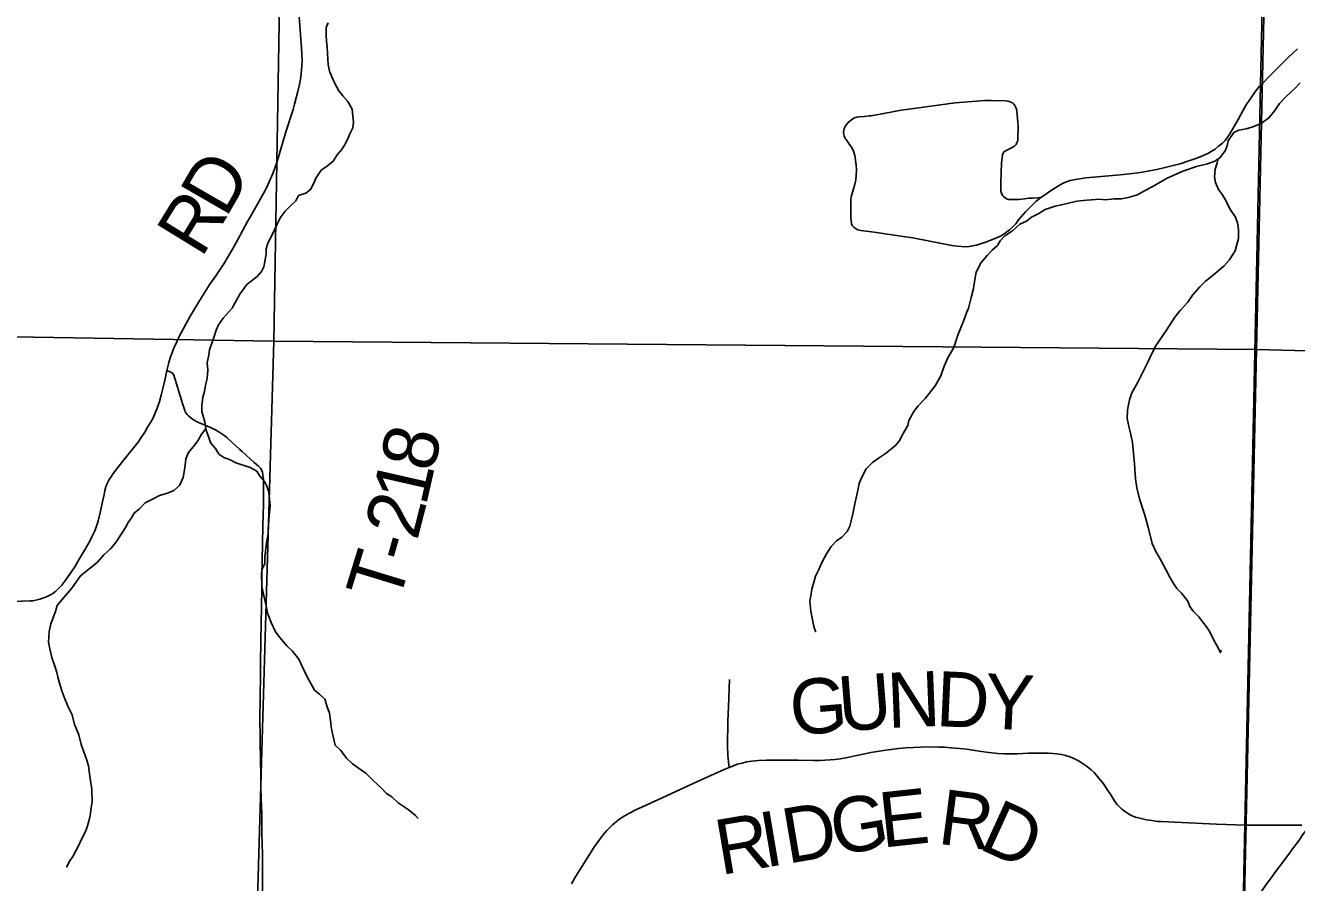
# Model space of a CAD drawing. Extents: x 0 to 34, y 0 to 22.
# Drawn here: x 5.283 to 6.594, y 15.364 to 16.248 of the extents above; entities that cross this region are included whole.
import ezdxf

# ---------------------------------------------------------------- set-up
doc = ezdxf.new("R2010")
doc.units = 0
for name, color, linetype in [('GM_X_Corporation', 7, 'Continuous'), ('GM_X_Interchange_Ramps', 7, 'Continuous'), ('GM_X_Interstate_Route', 7, 'Continuous'), ('GM_X_Major_Lake', 7, 'Continuous'), ('GM_X_Minor_Lake', 7, 'Continuous'), ('GM_X_Section', 7, 'Continuous'), ('GM_X_Township_Road_Text', 7, 'Continuous')]:
    doc.layers.add(name, color=color, linetype=linetype)

msp = doc.modelspace()

# ---------------------------------------------------------------- linework, layer by layer
at = {"layer": 'GM_X_Corporation'}
for points in [[(5.8464, 15.3632), (5.8509, 15.3708), (5.8574, 15.3813), (5.8649, 15.3933), (5.8702, 15.4016), (5.8766, 15.4105), (5.8803, 15.4152), (5.8828, 15.4182), (5.8859, 15.4213), (5.8888, 15.424), (5.8927, 15.4273), (5.8963, 15.43), (5.9006, 15.4327), (5.9055, 15.4356), (5.9129, 15.4394), (5.9198, 15.4426), (5.9317, 15.448), (5.9803, 15.4704), (6.0039, 15.4808), (6.0089, 15.483), (6.0136, 15.4849), (6.0174, 15.4863), (6.0224, 15.4876), (6.0269, 15.4887), (6.0324, 15.4894), (6.0392, 15.4902), (6.0476, 15.4906), (6.052, 15.4907), (6.0801, 15.4905), (6.0962, 15.4902), (6.1021, 15.4903), (6.1131, 15.4909), (6.1184, 15.4914), (6.1238, 15.4921), (6.1295, 15.4931), (6.1552, 15.4984), (6.1682, 15.5007), (6.1762, 15.5017), (6.1839, 15.5026), (6.1912, 15.5033), (6.1992, 15.5037), (6.2065, 15.504), (6.213, 15.5042), (6.2254, 15.504), (6.2313, 15.5039), (6.2381, 15.5034), (6.2509, 15.5022), (6.2563, 15.5015), (6.2671, 15.5), (6.2771, 15.4986), (6.2862, 15.4976), (6.2931, 15.4972), (6.2983, 15.4971), (6.3063, 15.4972), (6.3178, 15.4977), (6.3256, 15.4979), (6.3386, 15.4978), (6.3431, 15.4976), (6.3472, 15.497), (6.3519, 15.4963), (6.3559, 15.4954), (6.3595, 15.4942), (6.3631, 15.4929), (6.3661, 15.4916), (6.3695, 15.4898), (6.3733, 15.4875), (6.3774, 15.4847), (6.3825, 15.4806), (6.3857, 15.4777), (6.3871, 15.4763), (6.3926, 15.4697), (6.3951, 15.4663), (6.3989, 15.4605), (6.4035, 15.4537), (6.4071, 15.448), (6.4094, 15.445), (6.4118, 15.4424), (6.4141, 15.44), (6.4168, 15.4379), (6.4199, 15.4358), (6.4228, 15.4341), (6.4255, 15.4327), (6.4284, 15.4318), (6.434, 15.4303), (6.4396, 15.4291), (6.4452, 15.4282), (6.4511, 15.4275), (6.4548, 15.4272), (6.4761, 15.4262), (6.5117, 15.4247), (6.5414, 15.4237), (6.5471, 15.4235)], [(6.5452, 15.3343), (6.5495, 15.3413), (6.5548, 15.3499), (6.5578, 15.3549), (6.563, 15.3623), (6.5675, 15.3683), (6.5735, 15.3765), (6.5781, 15.3825), (6.583, 15.3891), (6.5864, 15.3936), (6.5904, 15.3992), (6.594, 15.404), (6.5973, 15.4086), (6.6007, 15.4135), (6.6049, 15.4191), (6.6077, 15.4229)], [(6.5471, 15.4235), (6.5841, 15.4236), (6.5999, 15.4237)]]:
    msp.add_lwpolyline(points, dxfattribs=at)
at = {"layer": 'GM_X_Interchange_Ramps'}
msp.add_lwpolyline([(2.1, 17.9098), (2.1, 14.1), (6.5113, 14.1), (6.5389, 15.3228), (6.5411, 15.4243), (6.5572, 16.1864), (6.5647, 16.5359), (6.5883, 17.471), (6.5943, 17.9356)], dxfattribs=at)
msp.add_lwpolyline([(6.5113, 14.1), (8.9, 14.1), (8.9, 17.8921), (8.5492, 17.9006), (8.3297, 17.9059), (7.6027, 17.9156), (6.5943, 17.9356), (6.5883, 17.471), (6.5647, 16.5359), (6.5572, 16.1864), (6.5411, 15.4243), (6.5389, 15.3228)], close=True, dxfattribs=at)
at = {"layer": 'GM_X_Interstate_Route'}
for points in [[(5.2695, 15.6542), (5.2879, 15.6547), (5.2906, 15.655), (5.2938, 15.6556), (5.2979, 15.6566), (5.3022, 15.658), (5.3056, 15.6592), (5.3089, 15.661), (5.3113, 15.6625), (5.3143, 15.6649), (5.3171, 15.6675), (5.3205, 15.6711), (5.3226, 15.6737), (5.3303, 15.6844), (5.334, 15.6899), (5.3396, 15.6994), (5.3448, 15.7081), (5.3495, 15.7165), (5.3517, 15.7209), (5.3545, 15.727), (5.3564, 15.7319), (5.3581, 15.737), (5.3592, 15.7414), (5.3602, 15.7458), (5.3618, 15.7537), (5.3642, 15.7646), (5.365, 15.7686), (5.3661, 15.7725), (5.3674, 15.7758), (5.3693, 15.7798), (5.3718, 15.7835), (5.3736, 15.786), (5.3831, 15.7986), (5.3992, 15.8186), (5.4026, 15.8234), (5.4062, 15.8288), (5.4091, 15.8338), (5.4121, 15.8387), (5.4144, 15.843), (5.4166, 15.8476), (5.4189, 15.8535), (5.4212, 15.8603), (5.4231, 15.8668), (5.4249, 15.8738), (5.4271, 15.8839), (5.4289, 15.8922), (5.4293, 15.8936), (5.4311, 15.9006), (5.4328, 15.9064), (5.4343, 15.9107), (5.4358, 15.9146), (5.4395, 15.9227), (5.4418, 15.9273), (5.4531, 15.9484), (5.4556, 15.9528), (5.4618, 15.9631), (5.4646, 15.9676), (5.4733, 15.9813), (5.4796, 15.9901), (5.4876, 16.0024), (5.4922, 16.0098), (5.4966, 16.0173), (5.5017, 16.0267), (5.5123, 16.0459), (5.5153, 16.0512), (5.529, 16.0754), (5.5319, 16.0808), (5.536, 16.0898), (5.5383, 16.0956), (5.5404, 16.1009), (5.5427, 16.1078), (5.551, 16.1359), (5.5521, 16.1396), (5.5591, 16.1613), (5.5607, 16.167), (5.5641, 16.1801), (5.5657, 16.1871), (5.5668, 16.1929), (5.5676, 16.1986), (5.5683, 16.2061), (5.5685, 16.2118), (5.5683, 16.2183), (5.5679, 16.2254), (5.5672, 16.234), (5.5642, 16.2762)], [(6.5726, 16.2019), (6.574, 16.2033), (6.5855, 16.2146), (6.5953, 16.224)], [(6.56, 16.1891), (6.5658, 16.195), (6.5698, 16.1991), (6.5726, 16.2019)], [(6.3047, 16.0435), (6.3077, 16.0476), (6.3101, 16.0506), (6.3124, 16.0532), (6.3148, 16.056), (6.3185, 16.0597), (6.3231, 16.0643), (6.3258, 16.0669), (6.3306, 16.0708), (6.3343, 16.0732), (6.3405, 16.0775), (6.3443, 16.08), (6.3505, 16.0838), (6.3538, 16.0855), (6.3579, 16.0871), (6.361, 16.0881), (6.3665, 16.0894), (6.3748, 16.0907), (6.377, 16.091), (6.4125, 16.0942), (6.4221, 16.0952), (6.4334, 16.0966), (6.4426, 16.0982), (6.4503, 16.0997), (6.459, 16.1016), (6.467, 16.1036), (6.4742, 16.1056), (6.4832, 16.1085), (6.4904, 16.111), (6.4966, 16.1133), (6.5011, 16.1153), (6.5035, 16.1164), (6.5064, 16.1181), (6.5104, 16.1207), (6.514, 16.1235), (6.518, 16.1269), (6.5206, 16.1295), (6.5226, 16.1319), (6.5242, 16.1343), (6.5255, 16.1363), (6.5341, 16.1512), (6.539, 16.16), (6.5426, 16.1662), (6.5471, 16.1733), (6.55, 16.1774), (6.5523, 16.1808), (6.5563, 16.1854), (6.56, 16.1891)], [(6.3047, 16.0435), (6.3018, 16.0404), (6.2982, 16.0375), (6.294, 16.0343), (6.2897, 16.0313), (6.2843, 16.0288), (6.2796, 16.0269), (6.274, 16.0248), (6.2684, 16.023), (6.2642, 16.0217), (6.2602, 16.0208), (6.2565, 16.0201), (6.2531, 16.0198), (6.2438, 16.0205), (6.2389, 16.0212), (6.1986, 16.029), (6.1887, 16.0306), (6.1588, 16.0349), (6.1449, 16.0368), (6.1417, 16.0375), (6.1395, 16.0386), (6.1376, 16.04), (6.1364, 16.0414), (6.1353, 16.0433), (6.1352, 16.0449), (6.1349, 16.0467), (6.1346, 16.0507), (6.1345, 16.0567), (6.1346, 16.0685), (6.1349, 16.0706), (6.1353, 16.0729), (6.1359, 16.0748), (6.1374, 16.0797), (6.1387, 16.0843), (6.1396, 16.0891), (6.1402, 16.0934), (6.1404, 16.0991), (6.14, 16.1041), (6.1386, 16.114), (6.1373, 16.1185), (6.1358, 16.1217), (6.1325, 16.1265), (6.1296, 16.1306), (6.1289, 16.1316), (6.1276, 16.1344), (6.1272, 16.1357), (6.1269, 16.1373), (6.1272, 16.1404), (6.1284, 16.1433), (6.1291, 16.1445), (6.1305, 16.1463), (6.132, 16.148), (6.134, 16.1498), (6.1366, 16.1518), (6.1385, 16.153), (6.1408, 16.1535), (6.143, 16.1539), (6.1487, 16.1544), (6.154, 16.1548), (6.1555, 16.155), (6.1686, 16.1574), (6.1864, 16.1606), (6.1921, 16.1614), (6.2423, 16.1683), (6.2468, 16.1688), (6.2642, 16.1702), (6.2729, 16.1707), (6.2796, 16.1708), (6.2942, 16.1705), (6.2967, 16.1701), (6.2991, 16.1694), (6.3007, 16.1686), (6.3018, 16.1679), (6.3027, 16.167), (6.3038, 16.1655), (6.3048, 16.1636), (6.3058, 16.1609), (6.306, 16.1596), (6.307, 16.1485), (6.3072, 16.1443), (6.3069, 16.1295), (6.306, 16.1273), (6.305, 16.1255), (6.3042, 16.1245), (6.3033, 16.1237), (6.3003, 16.122), (6.2962, 16.1199), (6.2926, 16.1177), (6.2912, 16.1147), (6.2906, 16.1117), (6.29, 16.1064), (6.2897, 16.0962), (6.2894, 16.0866), (6.2892, 16.0809), (6.2893, 16.079), (6.2894, 16.0772), (6.29, 16.0751), (6.291, 16.0729), (6.292, 16.0716), (6.2937, 16.0703), (6.2952, 16.0695), (6.2971, 16.0688), (6.2993, 16.0685), (6.3078, 16.0688), (6.3136, 16.0694), (6.3183, 16.0699), (6.3219, 16.0701), (6.3306, 16.0708)], [(5.528, 15.2935), (5.5278, 15.3828), (5.5275, 15.3941), (5.5272, 15.4035), (5.5271, 15.4142), (5.5269, 15.4324), (5.5268, 15.4359), (5.5266, 15.4411), (5.5265, 15.4443), (5.5264, 15.449), (5.5262, 15.4537), (5.526, 15.46), (5.5259, 15.4685), (5.5258, 15.4791), (5.5257, 15.4873), (5.5252, 15.5131), (5.5248, 15.5339), (5.5251, 15.553), (5.5253, 15.5624), (5.5255, 15.5719), (5.5256, 15.5768), (5.5257, 15.585), (5.526, 15.6189), (5.5262, 15.6271), (5.5267, 15.6535), (5.5268, 15.6628), (5.527, 15.6803), (5.5273, 15.6963), (5.528, 15.7318), (5.5287, 15.7545), (5.5286, 15.7803), (5.5284, 15.7815), (5.5275, 15.7878), (5.5271, 15.7889), (5.5263, 15.7907), (5.5255, 15.7918), (5.5235, 15.7938), (5.5192, 15.7976), (5.5069, 15.8084), (5.5041, 15.811), (5.492, 15.8223), (5.4905, 15.8237), (5.4858, 15.8271), (5.4836, 15.8285), (5.4792, 15.831), (5.4741, 15.8336), (5.4679, 15.8362), (5.4623, 15.8385), (5.4601, 15.8395), (5.4566, 15.8415), (5.4541, 15.8433), (5.4514, 15.8457), (5.45, 15.8471), (5.448, 15.8497), (5.4474, 15.851), (5.4453, 15.8573), (5.4361, 15.8874), (5.4356, 15.8886), (5.4349, 15.8896), (5.4342, 15.8901), (5.4331, 15.8907), (5.4303, 15.8918), (5.4289, 15.8922)], [(6.0089, 15.483), (6.0083, 15.4888), (6.0077, 15.4957), (6.0074, 15.5055), (6.0078, 15.5309), (6.0083, 15.5455), (6.0093, 15.5736)]]:
    msp.add_lwpolyline(points, dxfattribs=at)
at = {"layer": 'GM_X_Minor_Lake'}
for points in [[(4.539, 16.9739), (5.5566, 16.9477), (5.5393, 15.9226), (4.5275, 15.9394)], [(5.5566, 16.9477), (6.5754, 16.9273), (6.553, 15.9139), (5.5393, 15.9226)], [(7.5942, 16.9027), (7.5725, 15.8874), (6.553, 15.9139), (6.5754, 16.9273)], [(5.5393, 15.9226), (5.5097, 14.9125), (4.5059, 14.9222), (4.5275, 15.9394)], [(6.553, 15.9139), (6.5307, 14.8925), (5.5097, 14.9125), (5.5393, 15.9226)], [(7.5725, 15.8874), (7.5466, 14.8803), (6.5307, 14.8925), (6.553, 15.9139)]]:
    msp.add_lwpolyline(points, close=True, dxfattribs=at)
at = {"layer": 'GM_X_Township_Road_Text'}
for points in [[(5.5953, 16.2509), (5.5934, 16.2459), (5.5932, 16.2383), (5.5937, 16.2315), (5.5945, 16.2258), (5.5946, 16.2197), (5.5951, 16.2132), (5.5955, 16.2079), (5.5967, 16.201), (5.5991, 16.195), (5.6022, 16.1882), (5.6065, 16.1806), (5.6104, 16.1754), (5.6158, 16.1697), (5.62, 16.1618), (5.6209, 16.1546), (5.6214, 16.1485), (5.6207, 16.1424), (5.6178, 16.1363), (5.6152, 16.1305), (5.6122, 16.1248), (5.6093, 16.1198), (5.6048, 16.1148), (5.6004, 16.1082), (5.5948, 16.1032), (5.588, 16.0989), (5.5828, 16.0908), (5.5803, 16.0847), (5.5773, 16.0789), (5.5725, 16.0751), (5.5649, 16.0727), (5.562, 16.0673), (5.5567, 16.0626), (5.5511, 16.0565), (5.5459, 16.0499), (5.5368, 16.0308), (5.5331, 16.0238), (5.5313, 16.0177), (5.5313, 16.0128)], [(6.5983, 16.1891), (6.5924, 16.1829), (6.5838, 16.1748), (6.5767, 16.1675), (6.5719, 16.1605), (6.5659, 16.1528), (6.558, 16.147), (6.5483, 16.1434), (6.5426, 16.1414), (6.5347, 16.1402), (6.5298, 16.1378), (6.5239, 16.129), (6.5228, 16.124), (6.5206, 16.119), (6.5154, 16.1117), (6.5101, 16.1082), (6.5026, 16.1054), (6.4913, 16.1026), (6.477, 16.0978), (6.4601, 16.0903), (6.4454, 16.0817), (6.4368, 16.0774), (6.4304, 16.0735), (6.4206, 16.0707), (6.4138, 16.0694), (6.4066, 16.0693), (6.3971, 16.0684), (6.3915, 16.0691), (6.3782, 16.0681), (6.3676, 16.0668), (6.3578, 16.0644), (6.3518, 16.0632), (6.3454, 16.0619), (6.3352, 16.0584), (6.3284, 16.0541), (6.3209, 16.0505), (6.3157, 16.0463), (6.3089, 16.0431), (6.3014, 16.0365), (6.2936, 16.0311), (6.2887, 16.0261), (6.2858, 16.0211), (6.2805, 16.0164), (6.2753, 16.011), (6.269, 16.0037), (6.2638, 15.9937), (6.2624, 15.9861), (6.261, 15.9769), (6.2589, 15.9677), (6.2575, 15.962), (6.256, 15.9567), (6.2538, 15.9517), (6.2509, 15.9433), (6.2454, 15.9299), (6.2407, 15.9161), (6.2348, 15.9053), (6.2308, 15.8969), (6.2275, 15.8869), (6.2216, 15.8766), (6.2116, 15.8639), (6.2041, 15.8558)], [(6.5137, 16.1106), (6.5124, 16.1063), (6.5106, 16.0998), (6.5096, 16.0922), (6.5108, 16.0861), (6.514, 16.079), (6.5179, 16.0733), (6.5217, 16.0669), (6.5256, 16.059), (6.5314, 16.0503), (6.5334, 16.0446), (6.5346, 16.0378), (6.5344, 16.0286), (6.5326, 16.021), (6.5312, 16.0157), (6.5249, 16.006), (6.5197, 16.0002), (6.5137, 15.9952), (6.5085, 15.9906), (6.5006, 15.9844), (6.4946, 15.9786), (6.4872, 15.9701), (6.4824, 15.9628), (6.4745, 15.9543), (6.4689, 15.9473), (6.4604, 15.9339), (6.4534, 15.9239), (6.4493, 15.9177), (6.4456, 15.9104), (6.4405, 15.9001), (6.435, 15.8893), (6.4302, 15.8797), (6.4246, 15.8694), (6.4221, 15.8621), (6.42, 15.8518), (6.4197, 15.8427), (6.4218, 15.8332), (6.4234, 15.8264), (6.425, 15.818), (6.4259, 15.8104), (6.4264, 15.8032), (6.4272, 15.7963), (6.4277, 15.7906), (6.4282, 15.7808), (6.4295, 15.7713), (6.4323, 15.7599), (6.4374, 15.7443), (6.4414, 15.7307), (6.4455, 15.714), (6.4494, 15.7057), (6.454, 15.6974), (6.4599, 15.6865), (6.4638, 15.6793), (6.4676, 15.6729), (6.4708, 15.6676), (6.4757, 15.6627), (6.4823, 15.6544), (6.4843, 15.6491), (6.4878, 15.6442), (6.4935, 15.6382), (6.4978, 15.633), (6.5016, 15.6281), (6.5051, 15.6228), (6.5098, 15.613), (6.5133, 15.607), (6.516, 15.6013), (6.5168, 15.6039)], [(5.5313, 16.0128), (5.5299, 16.0048), (5.5289, 15.9994), (5.5267, 15.9944), (5.5222, 15.9894), (5.5114, 15.9809), (5.5043, 15.9709), (5.4991, 15.9617), (5.4962, 15.9567), (5.4872, 15.9463), (5.4824, 15.9393), (5.4799, 15.934), (5.4773, 15.9263), (5.473, 15.9137), (5.4723, 15.9084), (5.4705, 15.9003), (5.4714, 15.8927), (5.4707, 15.884), (5.4689, 15.8771), (5.4679, 15.8706), (5.4661, 15.8649), (5.4651, 15.8561), (5.4652, 15.85), (5.468, 15.8394), (5.4696, 15.8307), (5.4744, 15.8174), (5.479, 15.8118), (5.4825, 15.8061), (5.4878, 15.8028), (5.4943, 15.8002), (5.5, 15.7972), (5.5148, 15.7925), (5.5217, 15.7884), (5.5248, 15.7835), (5.5298, 15.7779), (5.5322, 15.773), (5.5341, 15.7669), (5.5355, 15.7532), (5.5345, 15.7426), (5.5336, 15.7292), (5.5336, 15.7239), (5.5319, 15.7147), (5.5302, 15.6999), (5.5299, 15.6934), (5.527, 15.6869), (5.5267, 15.6819), (5.5269, 15.6697), (5.5293, 15.6587), (5.5313, 15.6496), (5.5329, 15.642), (5.5365, 15.6326), (5.5412, 15.6228), (5.5454, 15.6171), (5.5527, 15.6085), (5.5585, 15.6028), (5.5651, 15.5946), (5.5693, 15.5859), (5.5733, 15.5772), (5.5814, 15.5628), (5.5864, 15.5587), (5.5918, 15.5535), (5.5945, 15.5455), (5.5969, 15.5391), (5.5978, 15.5315), (5.5986, 15.525), (5.5999, 15.5182), (5.6027, 15.506), (5.6084, 15.5004), (5.6142, 15.4925), (5.6204, 15.4869), (5.6254, 15.4832), (5.6342, 15.4772), (5.6422, 15.4693), (5.6499, 15.4622), (5.6557, 15.4562), (5.661, 15.4529), (5.6675, 15.4465), (5.6779, 15.4398), (5.6855, 15.4334), (5.6881, 15.4303)], [(6.2041, 15.8558), (6.1997, 15.85), (6.1945, 15.8408), (6.1934, 15.8358), (6.1875, 15.8258), (6.1853, 15.8205), (6.1805, 15.8151), (6.1752, 15.8104), (6.1704, 15.8069), (6.1633, 15.8019), (6.1569, 15.7976), (6.1505, 15.791), (6.1461, 15.7822), (6.1432, 15.776), (6.1414, 15.7673), (6.1386, 15.755), (6.1368, 15.7447), (6.135, 15.7375), (6.1336, 15.7317), (6.1307, 15.7264), (6.1254, 15.7206), (6.1198, 15.7167), (6.1142, 15.7109), (6.1094, 15.7032), (6.1046, 15.6944), (6.1017, 15.6871), (6.098, 15.6802), (6.0966, 15.6752), (6.0944, 15.6668), (6.0934, 15.66), (6.0923, 15.6546), (6.0932, 15.6443), (6.0949, 15.6352), (6.0965, 15.6284), (6.0981, 15.6231), (6.0985, 15.6239)], [(5.4692, 15.8327), (5.4644, 15.826), (5.4611, 15.8206), (5.4577, 15.8156), (5.4514, 15.8079), (5.4485, 15.8014), (5.4478, 15.7946), (5.4468, 15.7877), (5.4457, 15.782), (5.4421, 15.7739), (5.4361, 15.7685), (5.4297, 15.7657), (5.4214, 15.7633), (5.4135, 15.7594), (5.4067, 15.7559), (5.4008, 15.7497), (5.3951, 15.7454), (5.3926, 15.7405), (5.3892, 15.7355), (5.3863, 15.7305), (5.3815, 15.7228), (5.3763, 15.7151), (5.3707, 15.7085), (5.364, 15.7023), (5.3573, 15.6946), (5.3483, 15.6876), (5.3397, 15.6807), (5.3308, 15.668), (5.3207, 15.656), (5.3159, 15.6499), (5.3141, 15.6437), (5.3112, 15.6365), (5.3094, 15.6311), (5.3076, 15.6231), (5.307, 15.6124), (5.3082, 15.6052), (5.3102, 15.5965), (5.3138, 15.5866), (5.3154, 15.581), (5.3166, 15.576), (5.3186, 15.5688), (5.3206, 15.562), (5.3237, 15.5537), (5.3273, 15.5457), (5.3312, 15.5374), (5.3336, 15.5272), (5.3383, 15.5166), (5.3407, 15.5067), (5.3462, 15.4916), (5.3482, 15.4848), (5.3495, 15.4741), (5.3504, 15.4669), (5.3516, 15.4608), (5.3518, 15.4475), (5.3507, 15.4414), (5.3497, 15.4334), (5.3483, 15.4277), (5.3472, 15.4227), (5.3454, 15.4177), (5.3413, 15.4097), (5.3377, 15.4024), (5.3351, 15.397), (5.3318, 15.3913), (5.3281, 15.3859), (5.3259, 15.3805), (5.3262, 15.3824)]]:
    msp.add_lwpolyline(points, dxfattribs=at)

# ---------------------------------------------------------------- texts
at = {"layer": 'GM_X_Major_Lake'}
for s, rotation, p in [('U', 4.5546, (6.1237, 15.5199)), ('N', 2.2592, (6.173, 15.5238)), ('D', 357.3872, (6.2217, 15.5258)), ('Y', 357.1392, (6.2715, 15.5235)), ('G', 4.6021, (6.0739, 15.5159)), ('E', 6.2006, (6.1671, 15.4003)), ('G', 9.5815, (6.1186, 15.3921)), ('R', 352.6029, (6.2232, 15.4046)), ('D', 335.4343, (6.2652, 15.3999)), ('I', 9.6304, (6.0463, 15.3798)), ('D', 9.6222, (6.0693, 15.3837)), ('R', 9.6311, (6.0003, 15.372))]:
    msp.add_text(s, height=0.0568, rotation=rotation, dxfattribs=at).set_placement(p)
at = {"layer": 'GM_X_Section'}
for s, rotation, p in [('D', 60.0324, (5.4898, 16.0487)), ('R', 58.4505, (5.4645, 16.0074)), ('8', 77.7505, (5.704, 15.7864)), ('1', 77.1601, (5.6961, 15.7516)), ('2', 75.6437, (5.6871, 15.7161)), ('-', 74.1568, (5.6803, 15.6921)), ('T', 72.9366, (5.6674, 15.6502))]:
    msp.add_text(s, height=0.0568, rotation=rotation, dxfattribs=at).set_placement(p)

doc.saveas('drawing.dxf')
